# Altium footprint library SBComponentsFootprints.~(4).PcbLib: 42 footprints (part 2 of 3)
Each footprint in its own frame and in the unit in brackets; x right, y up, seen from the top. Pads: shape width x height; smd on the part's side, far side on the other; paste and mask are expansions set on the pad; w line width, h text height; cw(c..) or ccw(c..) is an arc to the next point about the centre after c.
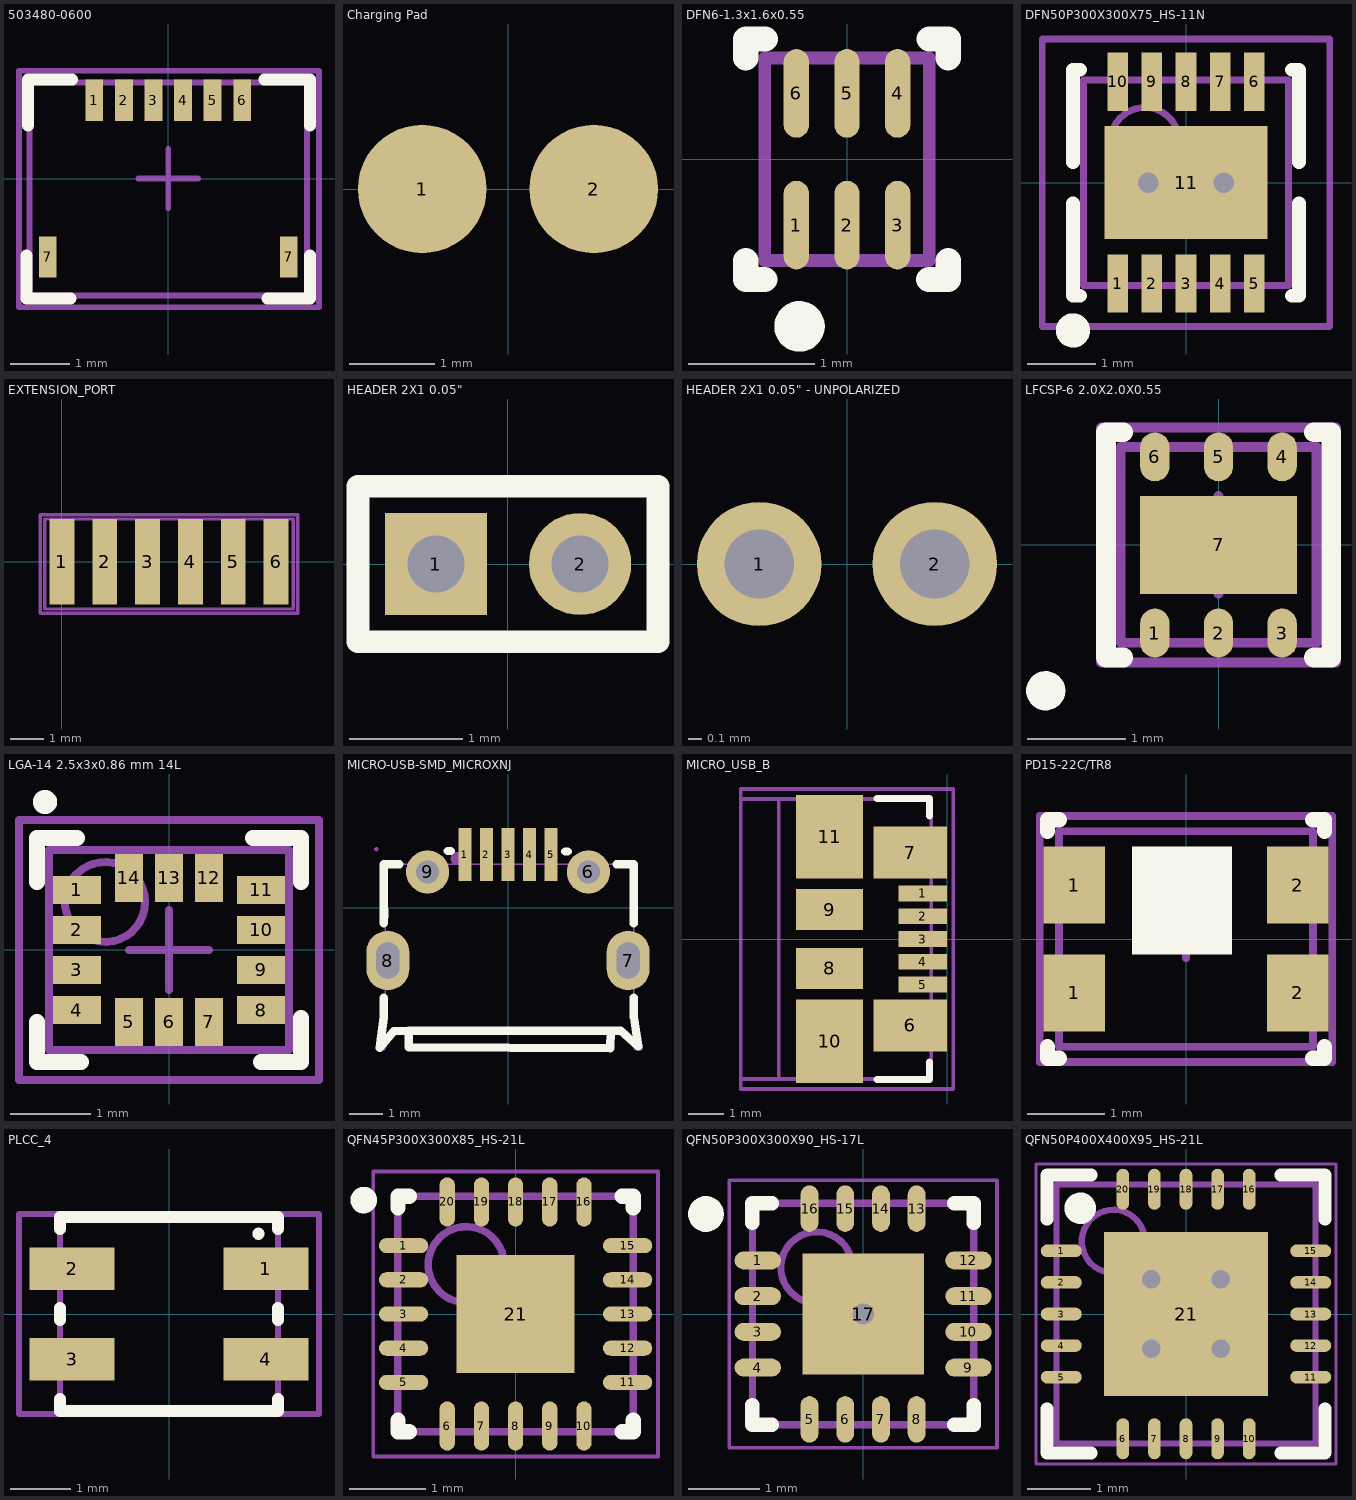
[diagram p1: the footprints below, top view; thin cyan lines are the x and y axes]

## 503480-0600 [mm]
height 1
pads (8):
  rect 0.3x0.7 smd: 1(-1.25,1.325) 2(-0.75,1.325) 3(-0.25,1.325) 4(0.25,1.325) 5(0.75,1.325) 6(1.25,1.325) 7(-2.04,-1.325) 7(2.04,-1.325)
Top Overlay:
  lines w0.2: -2.4,-1.3 -2.4,-2.025 -1.65,-2.025 ; -2.375,0.9 -2.375,1.675 -1.625,1.675 ; 1.625,1.675 2.4,1.675 2.4,0.9 ; 1.675,-2.025 2.4,-2.025 2.4,-1.3
Mechanical 1:
  lines w0.1: -2.35,-1.975 -2.35,1.625 2.35,1.625 2.35,-1.975 -2.35,-1.975
Mechanical 15:
  lines w0.1: -0.5,0 0.5,0 ; 0,-0.5 0,0.5 ; -2.525,-2.175 -2.525,1.825 2.55,1.825 2.55,-2.175 -2.525,-2.175
3D body "5034800600.stp": height 1.89, standoff -0.01, extent -2.35,-1.975 2.35,1.625

## Charging Pad [mm]
pads (2):
  round 1.5 smd paste-5: 1(-1,0) 2(1,0)
3D body: height 0, standoff 0, extent 0.252,-0.749 1.746,0.749
3D body: height 0, standoff 0, extent -1.744,-0.749 -0.25,0.749

## DFN6-1.3x1.6x0.55 [mm]
height 0.55
pads (6):
  oval 0.2x0.7 smd: 1(-0.4,-0.52) 2(0,-0.52) 3(0.4,-0.52) 4(0.4,0.52) 5(0,0.52) 6(-0.4,0.52)
Top Overlay:
  circle w0.2: c-0.375,-1.32 r0.1
  lines w0.2: -0.8,-0.8 -0.8,-0.95 -0.65,-0.95 ; -0.8,0.8 -0.8,0.95 -0.645,0.95 ; 0.645,-0.95 0.8,-0.95 0.8,-0.8 ; 0.65,0.95 0.8,0.95 0.8,0.8
Mechanical 13:
  lines w0.1: -0.65,-0.8 -0.65,0.8 0.65,0.8 0.65,-0.8 -0.65,-0.8
3D body: height 0.55, standoff 0, extent -0.65,-0.8 0.65,0.8

## DFN50P300X300X75_HS-11N [mm]
pads (11):
  rect 0.3x0.85 smd: 1(-1,-1.475) 2(-0.5,-1.475) 3(0,-1.475) 4(0.5,-1.475) 5(1,-1.475) 6(1,1.475) 7(0.5,1.475) 8(0,1.475) 9(-0.5,1.475) 10(-1,1.475)
  rect 2.38x1.65 smd: 11(0,0)
via 0.55,0 diameter 0.6 hole 0.3
via -0.55,0 diameter 0.6 hole 0.3
Top Overlay:
  circle w0.25: c-1.651,-2.159 r0.125
  lines w0.2: -1.65,-0.3 -1.65,-1.65 -1.55,-1.65 ; -1.65,0.3 -1.65,1.65 -1.55,1.65 ; 1.55,-1.65 1.65,-1.65 1.65,-0.3 ; 1.55,1.65 1.65,1.65 1.65,0.3
Mechanical 13:
  circle w0.1: c-0.6,0.6 r0.5
  lines w0.1: -1.5,-1.5 1.5,-1.5 1.5,1.5 -1.5,1.5 -1.5,-1.5
Mechanical 15:
  lines w0.1: -0.5,0 0.5,0 ; 0,-0.5 0,0.5 ; -2.1,-2.1 2.1,-2.1 2.1,2.1 -2.1,2.1 -2.1,-2.1
3D body: height 0.75, standoff 0, extent -1.5,-1.5 1.5,1.5

## EXTENSION_PORT [mil]
pads (6):
  rect 29x100 smd paste-78.74: 1(0,0) 2(50,0) 3(100,0) 4(150,0) 5(200,0) 6(250,0)
Mechanical 13:
  lines w3.94: -20,-55 270,-55 270,50 -20,50 -20,-55
Mechanical 15:
  lines w3.94: -25,-60 -25,55 275,55 275,-60 -25,-60
3D body: height 0.04, standoff 0, extent -15,-45 265,45

## HEADER 2X1 0.05" [mm]
pads (2):
  rect 0.9x0.9 hole 0.5: 1(-0.635,0)
  round 0.9 hole 0.5: 2(0.635,0)
Top Overlay:
  lines w0.2: -1.321,-0.686 -1.321,0.686 1.321,0.686 1.321,-0.686 -1.321,-0.686
3D body: height 0.01, standoff 0, extent -1.25,-0.6 1.25,0.6

## HEADER 2X1 0.05" - UNPOLARIZED [mm]
pads (2):
  round 0.9 hole 0.5: 1(-0.635,0) 2(0.635,0)
3D body: height 0.01, standoff 0, extent -1.25,-0.6 1.25,0.6

## LFCSP-6 2.0X2.0X0.55 [mm] ". 6-Lead Lead Frame Chip Scale Package [LFCSP_UD]  2.00 mm?2.00 mm Body, Ultra Thin, Dual Lead  (CP-6-3)"
height 0.55
pads (7):
  oval 0.3x0.5 smd: 1(-0.65,-0.9) 2(0,-0.9) 3(0.65,-0.9) 4(0.65,0.9) 5(0,0.9) 6(-0.65,0.9)
  rect 1.6x1 smd: 7(0,0)
Top Overlay:
  circle w0.2: c-1.765,-1.49 r0.1
  lines w0.2: -1.15,-1.15 -0.975,-1.15 ; -1.15,-1.125 -1.15,1.15 -0.975,1.15 ; 0.975,-1.15 1.15,-1.15 1.15,1.125 ; 0.975,1.15 1.15,1.15
Mechanical 13:
  lines w0.1: -1,-1 1,-1 1,1 -1,1 -1,-1
Mechanical 15:
  lines w0.1: -0.5,0 0.5,0 ; 0,-0.5 0,0.5 ; -1.2,-1.2 1.2,-1.2 1.2,1.2 -1.2,1.2 -1.2,-1.2
3D body: height 0.6, standoff 0.05, extent -1,-1 1,1

## LGA-14 2.5x3x0.86 mm 14L [mm] "LGA, 14-Leads, Body 3.00x2.50mm, Pitch 0.50mm, IPC High Density"
height 0.86
pads (14):
  rect 0.6x0.35 smd: 1(-1.15,0.75) 2(-1.15,0.25) 3(-1.15,-0.25) 4(-1.15,-0.75) 8(1.15,-0.75) 9(1.15,-0.25) 10(1.15,0.25) 11(1.15,0.75)
  rect 0.35x0.6 smd: 5(-0.5,-0.9) 6(0,-0.9) 7(0.5,-0.9) 12(0.5,0.9) 13(0,0.9) 14(-0.5,0.9)
Top Overlay:
  circle w0.2: c-1.55,1.85 r0.05
  lines w0.2: -1.65,-0.9 -1.65,-1.4 -1.1,-1.4 ; -1.65,0.85 -1.65,1.4 -1.15,1.4 ; 1.05,1.4 1.65,1.4 1.65,0.85 ; 1.15,-1.4 1.65,-1.4 1.65,-0.85
Mechanical 13:
  circle w0.1: c-0.8,0.6 r0.5
  lines w0.1: -1.5,-1.25 -1.5,1.25 1.5,1.25 1.5,-1.25 -1.5,-1.25
Mechanical 15:
  lines w0.1: -0.5,0 0.5,0 ; 0,-0.5 0,0.5 ; -1.875,-1.625 1.875,-1.625 1.875,1.625 -1.875,1.625 -1.875,-1.625
3D body: height 0.86, standoff 0.13, extent -1.5,-1.25 1.5,1.25

## MICRO-USB-SMD_MICROXNJ [mm]
pads (9):
  rect 0.4x1.6 smd paste-100 mask+0.051: 1(-1.3,1.596) 2(-0.65,1.596) 3(0,1.596) 4(0.65,1.596) 5(1.3,1.596)
  round 1.3 hole 0.7: 6(2.425,1.074) 9(-2.425,1.074)
  oval 1.3x1.8 hole 0.7 slot 1.1 at 90 deg: 7(3.625,-1.596) 8(-3.625,-1.596)
Top Overlay:
  lines w0.254: -3.745,-2.719 -3.745,-3.315 -3.87,-4.23 -3.45,-3.735 -3,-3.715 ; -3.745,-0.473 -3.745,1.31 -3.274,1.31 ; -3.735,-0.276 -3.731,-0.068 ; -3.733,-0.275 -3.732,-0.101 ; -1.814,1.707 -1.731,1.707 ; 1.731,1.693 1.799,1.693 ; 3.274,1.31 3.79,1.31 3.79,-0.481 ; 3.79,-3.304 3.79,-2.712 ; 3.8,-3.304 3.93,-4.19 3.4,-3.715 3.1,-3.715 ; -3,-3.715 3.1,-3.715 ; -3,-3.715 -3,-4.215 3.09,-4.245 3.1,-3.715
Top Paste:
  drawing of 9 lines, arcs and shapes, not listed
Mechanical 6:
  circle w0.2: c-1.53,1.479 r0.1
Mechanical 15:
  region: -3.91,1.766 -3.91,1.791 -3.945,1.826 -3.995,1.826 -4.03,1.791 -4.03,1.766 -4.03,1.741 -3.995,1.706 -3.945,1.706 -3.91,1.741
  region: -3.775,-1.141 -3.475,-1.141 -3.475,-2.051 -3.775,-2.051
  region: 3.475,-1.141 3.775,-1.141 3.775,-2.051 3.475,-2.051
  region: -2.675,0.974 -2.675,1.174 -2.175,1.174 -2.175,0.974
  region: 2.175,0.974 2.175,1.174 2.675,1.174 2.675,0.974
  region: -1.425,0.966 -1.425,1.966 -1.175,1.966 -1.175,0.966
  region: -0.775,0.966 -0.775,1.966 -0.525,1.966 -0.525,0.966
  region: -0.125,0.966 -0.125,1.966 0.125,1.966 0.125,0.966
  region: 0.525,0.966 0.525,1.966 0.775,1.966 0.775,0.966
  region: 1.175,0.966 1.175,1.966 1.425,1.966 1.425,0.966
  lines w0.051: -3.97,-4.281 -3.74,-4.291 -3.45,-3.691 -3.05,-3.691 -3.05,-4.281 -3.03,-4.281 3.15,-4.291 3.15,-3.691 3.54,-3.691 3.83,-4.281 4.03,-4.281 4.05,-4.221 3.79,-3.671 3.79,1.309 -3.7,1.309 -3.7,1.299 -3.7,-3.681 -3.97,-4.281

## MICRO_USB_B [mm]
pads (11):
  rect 1.38x0.45 smd: 1(-0.69,1.3) 2(-0.69,0.65) 3(-0.69,0) 4(-0.69,-0.65) 5(-0.69,-1.3)
  rect 2.1x1.475 smd: 6(-1.05,-2.462) 7(-1.05,2.462)
  rect 1.9x1.175 smd: 8(-3.35,-0.837) 9(-3.35,0.837)
  rect 1.9x2.375 smd: 10(-3.35,-2.913) 11(-3.35,2.913)
Top Overlay:
  lines w0.2: -2,-4 -0.5,-4 -0.5,-3.5 ; -2,4 -0.5,4 -0.5,3.5
Mechanical 1:
  lines w0.1: -5.88,3.99 -5.88,-3.99 -0.45,-3.99 ; -4.8,-4 -4.8,4
Mechanical 13:
  lines w0.1: -5.88,3.99 -0.45,3.99 -0.45,-3.99
Mechanical 15:
  lines w0.1: -5.875,-4.275 0.175,-4.275 0.175,4.275 -5.875,4.275 -5.875,-4.275
3D body "micro_usb.stp": height 2.69, standoff -0.25, extent -5.88,-3.99 -0.45,3.99

## PD15-22C/TR8 [mm] "Silicon PIN Photodiode"
height 1.1
pads (4):
  rect 0.8x1 smd: 1(-1.45,-0.7) 1(-1.45,0.7) 2(1.45,-0.7) 2(1.45,0.7)
Top Overlay:
  rectangle: -0.7,-0.2 0.6,1.2
  lines w0.2: -1.8,-1.4 -1.8,-1.55 -1.65,-1.55 ; -1.8,1.4 -1.8,1.55 -1.65,1.55 ; 1.65,-1.55 1.8,-1.55 1.8,-1.4 ; 1.65,1.55 1.8,1.55 1.8,1.4
Mechanical 1:
  lines w0.1: -1.65,-1.4 1.65,-1.4 1.65,1.4 -1.65,1.4 -1.65,-1.4
Mechanical 15:
  lines w0.1: -0.25,0 0.25,0 ; 0,-0.25 0,0.25 ; -1.9,-1.6 1.9,-1.6 1.9,1.6 -1.9,1.6 -1.9,-1.6
3D body: height 1.1, standoff 0, extent -1.65,-1.4 1.65,1.4

## PLCC_4 [mm]
height 1.9
pads (4):
  rect 1.4x0.7 smd: 1(1.6,0.75) 2(-1.6,0.75) 3(-1.6,-0.75) 4(1.6,-0.75)
Top Overlay:
  circle w0.2: c1.475,1.325 r0.001
  lines w0.2: -1.8,-1.4 -1.8,-1.6 1.8,-1.6 1.8,-1.4 ; -1.8,-0.1 -1.8,0.1 ; -1.8,1.4 -1.8,1.6 1.8,1.6 1.8,1.4 ; 1.8,-0.1 1.8,0.1
Mechanical 1:
  lines w0.1: -1.8,-1.6 1.8,-1.6 1.8,1.6 -1.8,1.6 -1.8,-1.6
Mechanical 15:
  lines w0.1: -2.475,-1.65 2.475,-1.65 2.475,1.65 -2.475,1.65 -2.475,-1.65
3D body: height 1.9, standoff 0, extent -1.8,-1.6 1.8,1.6

## QFN45P300X300X85_HS-21L [mm] "QFN, 20-Leads, Body 3.00x3.00mm, Pitch 0.45mm, Thermal Pad 1.55x1.55mm, IPC High Density"
height 0.85
pads (21):
  oval 0.65x0.2 smd: 1(-1.475,0.9) 2(-1.475,0.45) 3(-1.475,0) 4(-1.475,-0.45) 5(-1.475,-0.9) 11(1.475,-0.9) 12(1.475,-0.45) 13(1.475,0) 14(1.475,0.45) 15(1.475,0.9)
  oval 0.2x0.65 smd: 6(-0.9,-1.475) 7(-0.45,-1.475) 8(0,-1.475) 9(0.45,-1.475) 10(0.9,-1.475) 16(0.9,1.475) 17(0.45,1.475) 18(0,1.475) 19(-0.45,1.475) 20(-0.9,1.475)
  rect 1.55x1.55 smd: 21(0,0)
Top Overlay:
  circle w0.2: c-2,1.5 r0.075
  lines w0.2: -1.55,-1.4 -1.55,-1.55 -1.4,-1.55 ; -1.55,1.4 -1.55,1.55 -1.4,1.55 ; 1.4,-1.55 1.55,-1.55 1.55,-1.4 ; 1.4,1.55 1.55,1.55 1.55,1.4
Mechanical 13:
  circle w0.1: c-0.65,0.65 r0.5
  lines w0.1: -1.55,-1.55 -1.55,1.55 1.55,1.55 1.55,-1.55 -1.55,-1.55
Mechanical 15:
  lines w0.05: -1.875,-1.875 -1.875,1.875 1.875,1.875 1.875,-1.875 -1.875,-1.875
  lines w0.1: -0.5,0 0.5,0 ; 0,-0.5 0,0.5
3D body: height 0.85, standoff 0.05, extent -1.55,-1.55 1.55,1.55

## QFN50P300X300X90_HS-17L [mm] "QFN, 16-Leads, Body 3,00x3,00mm, Pitch 0,50mm, Thermal Pad 1,70x1,70mm, IPC High Density"
height 0.9
pads (17):
  oval 0.65x0.25 smd: 1(-1.475,0.75) 2(-1.475,0.25) 3(-1.475,-0.25) 4(-1.475,-0.75) 9(1.475,-0.75) 10(1.475,-0.25) 11(1.475,0.25) 12(1.475,0.75)
  oval 0.25x0.65 smd: 5(-0.75,-1.475) 6(-0.25,-1.475) 7(0.25,-1.475) 8(0.75,-1.475) 13(0.75,1.475) 14(0.25,1.475) 15(-0.25,1.475) 16(-0.75,1.475)
  rect 1.7x1.7 smd: 17(0,0)
via 0,0 diameter 0.6 hole 0.3
Top Overlay:
  circle w0.25: c-2.2,1.4 r0.125
  lines w0.2: -1.55,-1.275 -1.55,-1.55 -1.275,-1.55 ; -1.55,1.275 -1.55,1.55 -1.275,1.55 ; 1.275,-1.55 1.55,-1.55 1.55,-1.275 ; 1.275,1.55 1.55,1.55 1.55,1.275
Mechanical 13:
  circle w0.1: c-0.65,0.65 r0.5
  lines w0.1: -1.55,-1.55 1.55,-1.55 1.55,1.55 -1.55,1.55 -1.55,-1.55
Mechanical 15:
  lines w0.05: -1.875,-1.875 1.875,-1.875 1.875,1.875 -1.875,1.875 -1.875,-1.875
  lines w0.1: -0.5,0 0.5,0 ; 0,-0.5 0,0.5
3D body: height 0.9, standoff 0.05, extent -1.55,-1.55 1.55,1.55

## QFN50P400X400X95_HS-21L [mm] "QFN, 20-Leads, Body 4,00x4,00mm, Pitch 0,50mm, Thermal Pad 2,60x2,60mm, IPC High Density"
height 0.95
pads (21):
  oval 0.65x0.2 smd: 1(-1.975,1) 2(-1.975,0.5) 3(-1.975,0) 4(-1.975,-0.5) 5(-1.975,-1) 11(1.975,-1) 12(1.975,-0.5) 13(1.975,0) 14(1.975,0.5) 15(1.975,1)
  oval 0.2x0.65 smd: 6(-1,-1.975) 7(-0.5,-1.975) 8(0,-1.975) 9(0.5,-1.975) 10(1,-1.975) 16(1,1.975) 17(0.5,1.975) 18(0,1.975) 19(-0.5,1.975) 20(-1,1.975)
  rect 2.6x2.6 smd: 21(0,0)
via -0.55,0.55 diameter 0.6 hole 0.3
via 0.55,0.55 diameter 0.6 hole 0.3
via -0.55,-0.55 diameter 0.6 hole 0.3
via 0.55,-0.55 diameter 0.6 hole 0.3
Top Overlay:
  circle w0.25: c-1.675,1.675 r0.125
  lines w0.2: -2.2,-1.5 -2.2,-2.2 -1.5,-2.2 ; -2.2,1.5 -2.2,2.2 -1.5,2.2 ; 1.5,-2.2 2.2,-2.2 2.2,-1.5 ; 1.5,2.2 2.2,2.2 2.2,1.5
Mechanical 13:
  circle w0.1: c-1.15,1.15 r0.5
  lines w0.1: -2.05,-2.05 -2.05,2.05 2.05,2.05 2.05,-2.05 -2.05,-2.05
Mechanical 15:
  lines w0.05: -2.375,-2.375 -2.375,2.375 2.375,2.375 2.375,-2.375 -2.375,-2.375
  lines w0.1: -0.5,0 0.5,0 ; 0,-0.5 0,0.5
3D body: height 0.95, standoff 0.05, extent -2.05,-2.05 2.05,2.05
